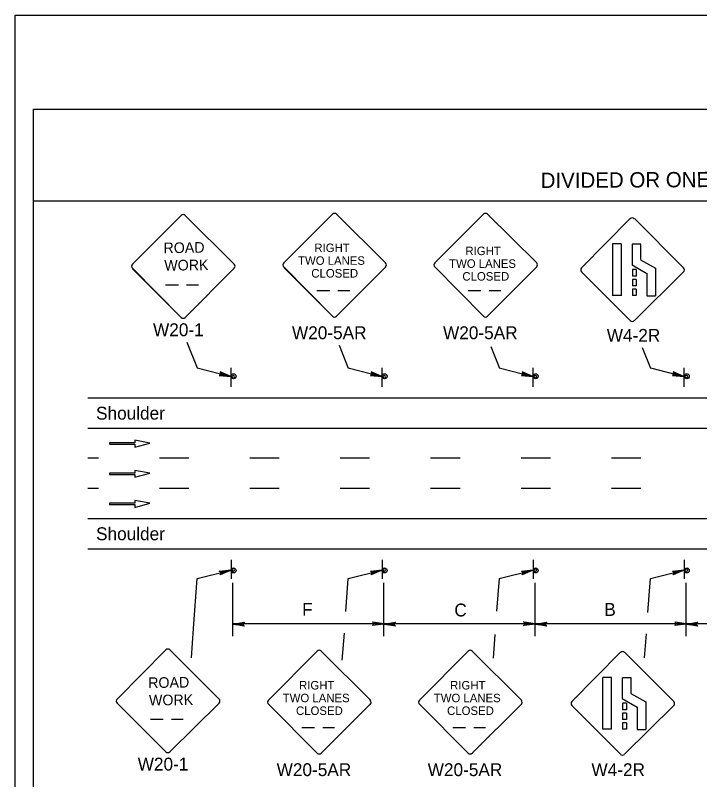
# Model space of a CAD drawing. Extents: x -14145 to -13521, y 30244 to 30661.
# Drawn here: x -13824.17 to -13813, y 30302.83 to 30315.31 of the extents above; entities that cross this region are included whole.
import ezdxf

# ---------------------------------------------------------------- set-up
doc = ezdxf.new("R2010")
doc.units = 0
for name, color, linetype in [('1', 7, 'Continuous'), ('10', 7, 'Continuous'), ('2', 7, 'Continuous'), ('4', 7, 'Continuous'), ('61', 7, 'Continuous')]:
    doc.layers.add(name, color=color, linetype=linetype)

msp = doc.modelspace()

# ---------------------------------------------------------------- linework, layer by layer
at = {"layer": '1'}
for p, q in [((-13822.262, 30311.244), (-13821.467, 30312.04)), ((-13821.401, 30312.04), (-13820.598, 30311.244)), ((-13819.792, 30311.266), (-13818.997, 30312.06)), ((-13818.93, 30312.06), (-13818.128, 30311.266)), ((-13817.326, 30311.266), (-13816.531, 30312.06)), ((-13816.464, 30312.06), (-13815.662, 30311.266)), ((-13814.134, 30311.988), (-13814.929, 30311.186)), ((-13814.134, 30311.988), (-13814.929, 30311.186)), ((-13813.264, 30311.186), (-13814.067, 30311.988)), ((-13813.264, 30311.186), (-13814.067, 30311.988)), ((-13814.426, 30311.578), (-13814.426, 30310.73)), ((-13814.426, 30311.578), (-13814.426, 30310.73)), ((-13814.281, 30311.577), (-13814.422, 30311.577)), ((-13814.281, 30311.577), (-13814.422, 30311.577)), ((-13814.285, 30311.578), (-13814.285, 30310.73)), ((-13814.285, 30311.578), (-13814.285, 30310.73)), ((-13814.106, 30311.572), (-13814.106, 30311.234)), ((-13814.106, 30311.572), (-13814.106, 30311.234)), ((-13813.961, 30311.572), (-13814.102, 30311.572)), ((-13813.961, 30311.572), (-13814.102, 30311.572)), ((-13813.965, 30311.572), (-13813.965, 30311.318)), ((-13813.965, 30311.572), (-13813.965, 30311.318)), ((-13813.965, 30311.315), (-13813.723, 30311.177)), ((-13813.965, 30311.315), (-13813.723, 30311.177)), ((-13818.997, 30310.396), (-13819.792, 30311.2)), ((-13818.996, 30310.396), (-13819.791, 30311.198)), ((-13819.791, 30311.191), (-13818.996, 30310.396)), ((-13819.791, 30311.19), (-13818.996, 30310.396)), ((-13818.127, 30311.2), (-13818.93, 30310.396)), ((-13816.531, 30310.396), (-13817.326, 30311.2)), ((-13815.661, 30311.2), (-13816.464, 30310.396)), ((-13814.106, 30311.232), (-13813.864, 30311.094)), ((-13814.106, 30311.232), (-13813.864, 30311.094)), ((-13821.467, 30310.376), (-13822.262, 30311.178)), ((-13822.262, 30311.171), (-13821.467, 30310.376)), ((-13822.262, 30311.17), (-13821.467, 30310.376)), ((-13820.598, 30311.178), (-13821.401, 30310.376)), ((-13814.929, 30311.12), (-13814.134, 30310.324)), ((-13814.929, 30311.12), (-13814.134, 30310.324)), ((-13814.1, 30311.156), (-13814.1, 30311.048)), ((-13814.036, 30311.156), (-13814.1, 30311.156)), ((-13814.1, 30311.156), (-13814.1, 30311.048)), ((-13814.036, 30311.156), (-13814.1, 30311.156)), ((-13814.067, 30310.324), (-13813.265, 30311.12)), ((-13814.067, 30310.324), (-13813.265, 30311.12)), ((-13814.036, 30311.156), (-13814.036, 30311.048)), ((-13814.036, 30311.156), (-13814.036, 30311.048)), ((-13813.864, 30311.096), (-13813.864, 30310.726)), ((-13813.864, 30311.096), (-13813.864, 30310.726)), ((-13813.723, 30311.178), (-13813.723, 30310.726)), ((-13813.723, 30311.178), (-13813.723, 30310.726)), ((-13814.036, 30311.048), (-13814.1, 30311.048)), ((-13814.036, 30311.048), (-13814.1, 30311.048)), ((-13814.1, 30310.995), (-13814.1, 30310.89)), ((-13814.036, 30310.995), (-13814.1, 30310.995)), ((-13814.1, 30310.995), (-13814.1, 30310.89)), ((-13814.036, 30310.995), (-13814.1, 30310.995)), ((-13814.036, 30310.995), (-13814.036, 30310.89)), ((-13814.036, 30310.995), (-13814.036, 30310.89)), ((-13821.72, 30310.909), (-13821.509, 30310.909)), ((-13821.377, 30310.909), (-13821.184, 30310.909)), ((-13814.036, 30310.89), (-13814.1, 30310.89)), ((-13814.036, 30310.89), (-13814.1, 30310.89)), ((-13814.036, 30310.838), (-13814.1, 30310.838)), ((-13814.1, 30310.838), (-13814.1, 30310.733)), ((-13814.036, 30310.838), (-13814.1, 30310.838)), ((-13814.1, 30310.838), (-13814.1, 30310.733)), ((-13814.036, 30310.838), (-13814.036, 30310.733)), ((-13814.036, 30310.838), (-13814.036, 30310.733)), ((-13819.249, 30310.812), (-13819.038, 30310.812)), ((-13818.906, 30310.812), (-13818.713, 30310.812)), ((-13816.783, 30310.812), (-13816.572, 30310.812)), ((-13816.44, 30310.812), (-13816.247, 30310.812)), ((-13814.281, 30310.731), (-13814.422, 30310.731)), ((-13814.281, 30310.731), (-13814.422, 30310.731)), ((-13814.036, 30310.733), (-13814.1, 30310.733)), ((-13814.036, 30310.733), (-13814.1, 30310.733)), ((-13813.724, 30310.724), (-13813.865, 30310.724)), ((-13813.724, 30310.724), (-13813.865, 30310.724)), ((-13821.374, 30309.973), (-13821.203, 30309.55)), ((-13818.887, 30309.921), (-13818.737, 30309.549)), ((-13816.413, 30309.9), (-13816.271, 30309.549)), ((-13813.94, 30309.883), (-13813.805, 30309.549)), ((-13821.204, 30309.55), (-13820.657, 30309.41)), ((-13820.651, 30309.242), (-13820.651, 30309.554)), ((-13820.651, 30309.242), (-13820.651, 30309.554)), ((-13818.738, 30309.55), (-13818.191, 30309.41)), ((-13818.185, 30309.242), (-13818.185, 30309.554)), ((-13818.185, 30309.242), (-13818.185, 30309.554)), ((-13816.272, 30309.55), (-13815.725, 30309.41)), ((-13815.719, 30309.242), (-13815.719, 30309.554)), ((-13815.719, 30309.242), (-13815.719, 30309.554)), ((-13813.806, 30309.55), (-13813.259, 30309.41)), ((-13813.253, 30309.242), (-13813.253, 30309.554)), ((-13813.253, 30309.242), (-13813.253, 30309.554)), ((-13822.991, 30309.06), (-13793.191, 30309.06)), ((-13822.991, 30308.568), (-13793.191, 30308.568)), ((-13822.223, 30308.326), (-13822.637, 30308.326)), ((-13822.637, 30308.326), (-13822.637, 30308.304)), ((-13821.979, 30308.325), (-13822.223, 30308.371)), ((-13822.223, 30308.371), (-13822.223, 30308.326)), ((-13822.221, 30308.259), (-13821.979, 30308.325)), ((-13822.637, 30308.304), (-13822.221, 30308.304)), ((-13822.221, 30308.304), (-13822.221, 30308.259)), ((-13822.817, 30308.076), (-13822.991, 30308.076)), ((-13821.341, 30308.076), (-13821.821, 30308.076)), ((-13819.865, 30308.076), (-13820.345, 30308.076)), ((-13818.389, 30308.076), (-13818.869, 30308.076)), ((-13816.913, 30308.076), (-13817.393, 30308.076)), ((-13815.437, 30308.076), (-13815.917, 30308.076)), ((-13813.961, 30308.076), (-13814.441, 30308.076)), ((-13822.223, 30307.834), (-13822.637, 30307.834)), ((-13822.637, 30307.834), (-13822.637, 30307.812)), ((-13821.979, 30307.833), (-13822.223, 30307.879)), ((-13822.223, 30307.879), (-13822.223, 30307.834)), ((-13822.221, 30307.767), (-13821.979, 30307.833)), ((-13822.637, 30307.812), (-13822.221, 30307.812)), ((-13822.221, 30307.812), (-13822.221, 30307.767)), ((-13822.817, 30307.584), (-13822.991, 30307.584)), ((-13821.341, 30307.584), (-13821.821, 30307.584)), ((-13819.865, 30307.584), (-13820.345, 30307.584)), ((-13818.389, 30307.584), (-13818.869, 30307.584)), ((-13816.913, 30307.584), (-13817.393, 30307.584)), ((-13815.437, 30307.584), (-13815.917, 30307.584)), ((-13813.961, 30307.584), (-13814.441, 30307.584)), ((-13822.223, 30307.342), (-13822.637, 30307.342)), ((-13822.637, 30307.342), (-13822.637, 30307.32)), ((-13821.979, 30307.341), (-13822.223, 30307.387)), ((-13822.223, 30307.387), (-13822.223, 30307.342)), ((-13822.221, 30307.275), (-13821.979, 30307.341)), ((-13822.637, 30307.32), (-13822.221, 30307.32)), ((-13822.221, 30307.32), (-13822.221, 30307.275)), ((-13822.991, 30307.092), (-13803.495, 30307.092)), ((-13822.991, 30306.6), (-13793.191, 30306.6)), ((-13820.651, 30306.418), (-13820.651, 30306.106)), ((-13820.651, 30306.418), (-13820.651, 30306.106)), ((-13818.185, 30306.418), (-13818.185, 30306.106)), ((-13818.185, 30306.418), (-13818.185, 30306.106)), ((-13815.719, 30306.418), (-13815.719, 30306.106)), ((-13815.719, 30306.418), (-13815.719, 30306.106)), ((-13813.253, 30306.418), (-13813.253, 30306.106)), ((-13813.253, 30306.418), (-13813.253, 30306.106)), ((-13821.204, 30306.112), (-13820.657, 30306.252)), ((-13818.738, 30306.112), (-13818.191, 30306.252)), ((-13816.272, 30306.112), (-13815.725, 30306.252)), ((-13813.806, 30306.112), (-13813.259, 30306.252)), ((-13821.263, 30305.299), (-13821.203, 30306.111)), ((-13818.776, 30305.573), (-13818.737, 30306.111)), ((-13816.31, 30305.582), (-13816.271, 30306.111)), ((-13813.846, 30305.557), (-13813.805, 30306.111)), ((-13820.621, 30305.17), (-13820.621, 30306.044)), ((-13818.155, 30305.17), (-13818.155, 30306.044)), ((-13815.689, 30305.17), (-13815.689, 30306.044)), ((-13813.223, 30305.17), (-13813.223, 30306.044)), ((-13818.155, 30305.374), (-13820.621, 30305.374)), ((-13815.689, 30305.374), (-13818.155, 30305.374)), ((-13813.223, 30305.374), (-13815.689, 30305.374)), ((-13810.757, 30305.374), (-13813.223, 30305.374)), ((-13821.298, 30304.821), (-13821.263, 30305.299)), ((-13818.835, 30304.778), (-13818.802, 30305.223)), ((-13813.9, 30304.818), (-13813.871, 30305.208)), ((-13816.366, 30304.814), (-13816.338, 30305.198)), ((-13821.717, 30304.95), (-13822.512, 30304.146)), ((-13820.848, 30304.146), (-13821.651, 30304.95)), ((-13819.247, 30304.928), (-13820.042, 30304.126)), ((-13818.377, 30304.126), (-13819.18, 30304.928)), ((-13816.781, 30304.928), (-13817.576, 30304.126)), ((-13815.911, 30304.126), (-13816.714, 30304.928)), ((-13814.293, 30304.91), (-13815.088, 30304.106)), ((-13814.293, 30304.91), (-13815.088, 30304.106)), ((-13813.423, 30304.106), (-13814.226, 30304.91)), ((-13813.423, 30304.106), (-13814.226, 30304.91)), ((-13814.585, 30304.498), (-13814.585, 30303.652)), ((-13814.585, 30304.498), (-13814.585, 30303.652)), ((-13814.44, 30304.498), (-13814.581, 30304.498)), ((-13814.44, 30304.498), (-13814.581, 30304.498)), ((-13814.444, 30304.498), (-13814.444, 30303.652)), ((-13814.444, 30304.498), (-13814.444, 30303.652)), ((-13814.265, 30304.494), (-13814.265, 30304.156)), ((-13814.265, 30304.494), (-13814.265, 30304.156)), ((-13814.12, 30304.494), (-13814.261, 30304.494)), ((-13814.12, 30304.494), (-13814.261, 30304.494)), ((-13814.124, 30304.494), (-13814.124, 30304.238)), ((-13814.124, 30304.494), (-13814.124, 30304.238)), ((-13814.124, 30304.236), (-13813.882, 30304.098)), ((-13814.124, 30304.236), (-13813.882, 30304.098)), ((-13822.512, 30304.081), (-13821.717, 30303.286)), ((-13822.512, 30304.08), (-13821.717, 30303.286)), ((-13821.651, 30303.286), (-13820.848, 30304.08)), ((-13814.265, 30304.153), (-13814.023, 30304.015)), ((-13814.265, 30304.153), (-13814.023, 30304.015)), ((-13814.259, 30304.077), (-13814.259, 30303.969)), ((-13814.195, 30304.077), (-13814.259, 30304.077)), ((-13814.259, 30304.077), (-13814.259, 30303.969)), ((-13814.195, 30304.077), (-13814.259, 30304.077)), ((-13814.195, 30304.077), (-13814.195, 30303.969)), ((-13814.195, 30304.077), (-13814.195, 30303.969)), ((-13813.882, 30304.1), (-13813.882, 30303.646)), ((-13813.882, 30304.1), (-13813.882, 30303.646)), ((-13820.042, 30304.06), (-13819.247, 30303.264)), ((-13819.18, 30303.264), (-13818.378, 30304.06)), ((-13817.576, 30304.06), (-13816.781, 30303.264)), ((-13816.714, 30303.264), (-13815.912, 30304.06)), ((-13815.088, 30304.04), (-13814.293, 30303.246)), ((-13815.088, 30304.04), (-13814.293, 30303.246)), ((-13814.195, 30303.969), (-13814.259, 30303.969)), ((-13814.195, 30303.969), (-13814.259, 30303.969)), ((-13814.226, 30303.246), (-13813.424, 30304.04)), ((-13814.226, 30303.246), (-13813.424, 30304.04)), ((-13814.023, 30304.016), (-13814.023, 30303.646)), ((-13814.023, 30304.016), (-13814.023, 30303.646)), ((-13814.259, 30303.916), (-13814.259, 30303.811)), ((-13814.195, 30303.916), (-13814.259, 30303.916)), ((-13814.259, 30303.916), (-13814.259, 30303.811)), ((-13814.195, 30303.916), (-13814.259, 30303.916)), ((-13814.195, 30303.916), (-13814.195, 30303.811)), ((-13814.195, 30303.916), (-13814.195, 30303.811)), ((-13821.969, 30303.819), (-13821.759, 30303.819)), ((-13821.626, 30303.819), (-13821.433, 30303.819)), ((-13814.195, 30303.811), (-13814.259, 30303.811)), ((-13814.195, 30303.811), (-13814.259, 30303.811)), ((-13814.195, 30303.759), (-13814.259, 30303.759)), ((-13814.259, 30303.759), (-13814.259, 30303.654)), ((-13814.195, 30303.759), (-13814.259, 30303.759)), ((-13814.259, 30303.759), (-13814.259, 30303.654)), ((-13814.195, 30303.759), (-13814.195, 30303.654)), ((-13814.195, 30303.759), (-13814.195, 30303.654)), ((-13819.498, 30303.68), (-13819.288, 30303.68)), ((-13819.155, 30303.68), (-13818.962, 30303.68)), ((-13817.032, 30303.68), (-13816.822, 30303.68)), ((-13816.689, 30303.68), (-13816.496, 30303.68)), ((-13814.44, 30303.652), (-13814.581, 30303.652)), ((-13814.44, 30303.652), (-13814.581, 30303.652)), ((-13814.195, 30303.654), (-13814.259, 30303.654)), ((-13814.195, 30303.654), (-13814.259, 30303.654)), ((-13813.882, 30303.645), (-13814.023, 30303.645)), ((-13813.882, 30303.645), (-13814.023, 30303.645))]:
    msp.add_line(p, q, dxfattribs=at)
for points in [[(-13820.837, 30309.434), (-13820.825, 30309.446), (-13820.657, 30309.41), (-13820.837, 30309.434), (-13820.843, 30309.428), (-13820.657, 30309.41), (-13820.819, 30309.464), (-13820.825, 30309.476), (-13820.657, 30309.41), (-13820.831, 30309.488), (-13820.825, 30309.476)], [(-13818.371, 30309.434), (-13818.359, 30309.446), (-13818.191, 30309.41), (-13818.371, 30309.434), (-13818.377, 30309.428), (-13818.191, 30309.41), (-13818.353, 30309.464), (-13818.359, 30309.476), (-13818.191, 30309.41), (-13818.365, 30309.488), (-13818.359, 30309.476)], [(-13815.905, 30309.434), (-13815.893, 30309.446), (-13815.725, 30309.41), (-13815.905, 30309.434), (-13815.911, 30309.428), (-13815.725, 30309.41), (-13815.887, 30309.464), (-13815.893, 30309.476), (-13815.725, 30309.41), (-13815.899, 30309.488), (-13815.893, 30309.476)], [(-13813.439, 30309.434), (-13813.427, 30309.446), (-13813.259, 30309.41), (-13813.439, 30309.434), (-13813.445, 30309.428), (-13813.259, 30309.41), (-13813.421, 30309.464), (-13813.427, 30309.476), (-13813.259, 30309.41), (-13813.433, 30309.488), (-13813.427, 30309.476)], [(-13820.837, 30306.228), (-13820.825, 30306.216), (-13820.657, 30306.252), (-13820.837, 30306.228), (-13820.843, 30306.234), (-13820.657, 30306.252), (-13820.819, 30306.198), (-13820.825, 30306.186), (-13820.657, 30306.252), (-13820.831, 30306.174), (-13820.825, 30306.186)], [(-13818.371, 30306.228), (-13818.359, 30306.216), (-13818.191, 30306.252), (-13818.371, 30306.228), (-13818.377, 30306.234), (-13818.191, 30306.252), (-13818.353, 30306.198), (-13818.359, 30306.186), (-13818.191, 30306.252), (-13818.365, 30306.174), (-13818.359, 30306.186)], [(-13815.905, 30306.228), (-13815.893, 30306.216), (-13815.725, 30306.252), (-13815.905, 30306.228), (-13815.911, 30306.234), (-13815.725, 30306.252), (-13815.887, 30306.198), (-13815.893, 30306.186), (-13815.725, 30306.252), (-13815.899, 30306.174), (-13815.893, 30306.186)], [(-13813.439, 30306.228), (-13813.427, 30306.216), (-13813.259, 30306.252), (-13813.439, 30306.228), (-13813.445, 30306.234), (-13813.259, 30306.252), (-13813.421, 30306.198), (-13813.427, 30306.186), (-13813.259, 30306.252), (-13813.433, 30306.174), (-13813.427, 30306.186)], [(-13820.441, 30305.344), (-13820.447, 30305.356), (-13820.621, 30305.368), (-13820.441, 30305.344), (-13820.435, 30305.338), (-13820.621, 30305.368), (-13820.447, 30305.374), (-13820.441, 30305.386), (-13820.621, 30305.368), (-13820.435, 30305.398), (-13820.441, 30305.386)], [(-13818.335, 30305.398), (-13818.329, 30305.38), (-13818.155, 30305.374), (-13818.335, 30305.398), (-13818.341, 30305.404), (-13818.155, 30305.374), (-13818.329, 30305.368), (-13818.335, 30305.35), (-13818.155, 30305.374), (-13818.341, 30305.344), (-13818.335, 30305.35)], [(-13817.975, 30305.344), (-13817.981, 30305.356), (-13818.155, 30305.368), (-13817.975, 30305.344), (-13817.969, 30305.338), (-13818.155, 30305.368), (-13817.981, 30305.374), (-13817.975, 30305.386), (-13818.155, 30305.368), (-13817.969, 30305.398), (-13817.975, 30305.386)], [(-13815.869, 30305.398), (-13815.863, 30305.38), (-13815.689, 30305.374), (-13815.869, 30305.398), (-13815.875, 30305.404), (-13815.689, 30305.374), (-13815.863, 30305.368), (-13815.869, 30305.35), (-13815.689, 30305.374), (-13815.875, 30305.344), (-13815.869, 30305.35)], [(-13815.509, 30305.344), (-13815.515, 30305.356), (-13815.689, 30305.368), (-13815.509, 30305.344), (-13815.503, 30305.338), (-13815.689, 30305.368), (-13815.515, 30305.374), (-13815.509, 30305.386), (-13815.689, 30305.368), (-13815.503, 30305.398), (-13815.509, 30305.386)], [(-13813.403, 30305.398), (-13813.397, 30305.38), (-13813.223, 30305.374), (-13813.403, 30305.398), (-13813.409, 30305.404), (-13813.223, 30305.374), (-13813.397, 30305.368), (-13813.403, 30305.35), (-13813.223, 30305.374), (-13813.409, 30305.344), (-13813.403, 30305.35)], [(-13813.043, 30305.344), (-13813.049, 30305.356), (-13813.223, 30305.368), (-13813.043, 30305.344), (-13813.037, 30305.338), (-13813.223, 30305.368), (-13813.049, 30305.374), (-13813.043, 30305.386), (-13813.223, 30305.368), (-13813.037, 30305.398), (-13813.043, 30305.386)]]:
    msp.add_lwpolyline(points, dxfattribs=at)
for centre in [(-13820.611, 30309.415), (-13818.145, 30309.415), (-13815.679, 30309.415), (-13813.213, 30309.415), (-13820.611, 30306.245), (-13818.145, 30306.245), (-13815.679, 30306.245), (-13813.213, 30306.245)]:
    msp.add_circle(centre, 0.0408, dxfattribs=at)
for centre, radius, start, end in [((-13818.964, 30312.027), 0.0465, 45, 135), ((-13816.498, 30312.027), 0.0465, 45, 135), ((-13821.434, 30312.006), 0.0465, 45, 135), ((-13814.101, 30311.953), 0.0465, 45, 135), ((-13814.101, 30311.953), 0.0465, 45, 135), ((-13822.229, 30311.21), 0.0465, 135, 225), ((-13820.631, 30311.211), 0.0465, 315, 45), ((-13819.759, 30311.231), 0.0465, 135, 225), ((-13818.161, 30311.232), 0.0465, 315, 45), ((-13817.293, 30311.231), 0.0465, 135, 225), ((-13815.695, 30311.232), 0.0465, 315, 45), ((-13814.896, 30311.151), 0.0465, 135, 225), ((-13814.896, 30311.151), 0.0465, 135, 225), ((-13813.298, 30311.15), 0.0465, 315, 45), ((-13813.298, 30311.15), 0.0465, 315, 45), ((-13821.434, 30310.408), 0.0465, 225, 315), ((-13818.964, 30310.428), 0.0465, 225, 315), ((-13816.498, 30310.428), 0.0465, 225, 315), ((-13814.101, 30310.355), 0.0465, 225, 315), ((-13814.101, 30310.355), 0.0465, 225, 315), ((-13820.616, 30309.407), 0.0214, 175.7499, 170.479), ((-13818.15, 30309.407), 0.0214, 175.7499, 170.479), ((-13815.684, 30309.407), 0.0214, 175.7499, 170.479), ((-13813.218, 30309.407), 0.0214, 175.7499, 170.479), ((-13820.616, 30306.253), 0.0214, 189.521, 184.2501), ((-13818.15, 30306.253), 0.0214, 189.521, 184.2501), ((-13815.684, 30306.253), 0.0214, 189.521, 184.2501), ((-13813.218, 30306.253), 0.0214, 189.521, 184.2501), ((-13821.683, 30304.916), 0.0465, 45, 135), ((-13819.214, 30304.895), 0.0465, 45, 135), ((-13816.748, 30304.895), 0.0465, 45, 135), ((-13814.26, 30304.874), 0.0465, 45, 135), ((-13814.26, 30304.874), 0.0465, 45, 135), ((-13822.478, 30304.113), 0.0465, 135, 225), ((-13820.88, 30304.113), 0.0465, 315, 45), ((-13820.009, 30304.093), 0.0465, 135, 225), ((-13818.411, 30304.092), 0.0465, 315, 45), ((-13817.543, 30304.093), 0.0465, 135, 225), ((-13815.945, 30304.092), 0.0465, 315, 45), ((-13815.055, 30304.072), 0.0465, 135, 225), ((-13815.055, 30304.072), 0.0465, 135, 225), ((-13813.457, 30304.071), 0.0465, 315, 45), ((-13813.457, 30304.071), 0.0465, 315, 45), ((-13821.683, 30303.318), 0.0465, 225, 315), ((-13819.214, 30303.297), 0.0465, 225, 315), ((-13816.748, 30303.297), 0.0465, 225, 315), ((-13814.26, 30303.276), 0.0465, 225, 315), ((-13814.26, 30303.276), 0.0465, 225, 315)]:
    msp.add_arc(centre, radius, start, end, dxfattribs=at)
at = {"layer": '10'}
for p, q in [((-13823.874, 30313.777), (-13792.422, 30313.777)), ((-13823.874, 30291.207), (-13823.874, 30313.777)), ((-13823.874, 30312.277), (-13792.422, 30312.277))]:
    msp.add_line(p, q, dxfattribs=at)
at = {"layer": '61'}
msp.add_lwpolyline([(-13824.174, 30315.307), (-13791.174, 30315.307), (-13791.174, 30289.807), (-13824.174, 30289.807)], close=True, dxfattribs=at)

# ---------------------------------------------------------------- texts
at = {"layer": '1'}
for s, height, rotation, p in [('ROAD', 0.1735, 0.7566, (-13821.753, 30311.423)), ('WORK', 0.1733, 0.7588, (-13821.74, 30311.138)), ('ROAD', 0.1735, 0.7566, (-13822.003, 30304.325)), ('WORK', 0.1733, 0.7588, (-13821.99, 30304.04))]:
    msp.add_text(s, height=height, rotation=rotation, dxfattribs=at).set_placement(p)
for s, height, p in [('RIGHT', 0.1386, (-13819.291, 30311.442)), ('RIGHT', 0.1386, (-13816.825, 30311.392)), ('TWO LANES', 0.1386, (-13819.557, 30311.234)), ('TWO LANES', 0.1386, (-13817.091, 30311.184)), ('CLOSED', 0.1389, (-13819.341, 30311.026)), ('CLOSED', 0.1389, (-13816.875, 30310.976)), ('RIGHT', 0.1386, (-13819.541, 30304.302)), ('RIGHT', 0.1386, (-13817.075, 30304.302)), ('TWO LANES', 0.1386, (-13819.807, 30304.094)), ('TWO LANES', 0.1386, (-13817.341, 30304.094)), ('CLOSED', 0.1389, (-13819.591, 30303.886)), ('CLOSED', 0.1389, (-13817.125, 30303.886))]:
    msp.add_text(s, height=height, dxfattribs=at).set_placement(p)
at = {"layer": '2'}
for s, p in [('W20-1', (-13821.925, 30310.069)), ('W20-5AR', (-13819.657, 30310.02)), ('W20-5AR', (-13817.191, 30310.02)), ('W4-2R', (-13814.518, 30309.977)), ('Shoulder', (-13822.855, 30308.707)), ('Shoulder', (-13822.855, 30306.739)), ('F', (-13819.491, 30305.506)), ('C', (-13817.006, 30305.494)), ('B', (-13814.558, 30305.503)), ('W20-1', (-13822.175, 30302.979)), ('W20-5AR', (-13819.907, 30302.888)), ('W20-5AR', (-13817.441, 30302.888)), ('W4-2R', (-13814.768, 30302.887))]:
    msp.add_text(s, height=0.21, dxfattribs=at).set_placement(p)
at = {"layer": '4'}
msp.add_text('DIVIDED OR ONE-WAY HIGHWAY - WORK AREA IN TWO ADJACENT LANES', height=0.25, rotation=0.31, dxfattribs=at).set_placement((-13815.597, 30312.487))

doc.saveas('drawing.dxf')
